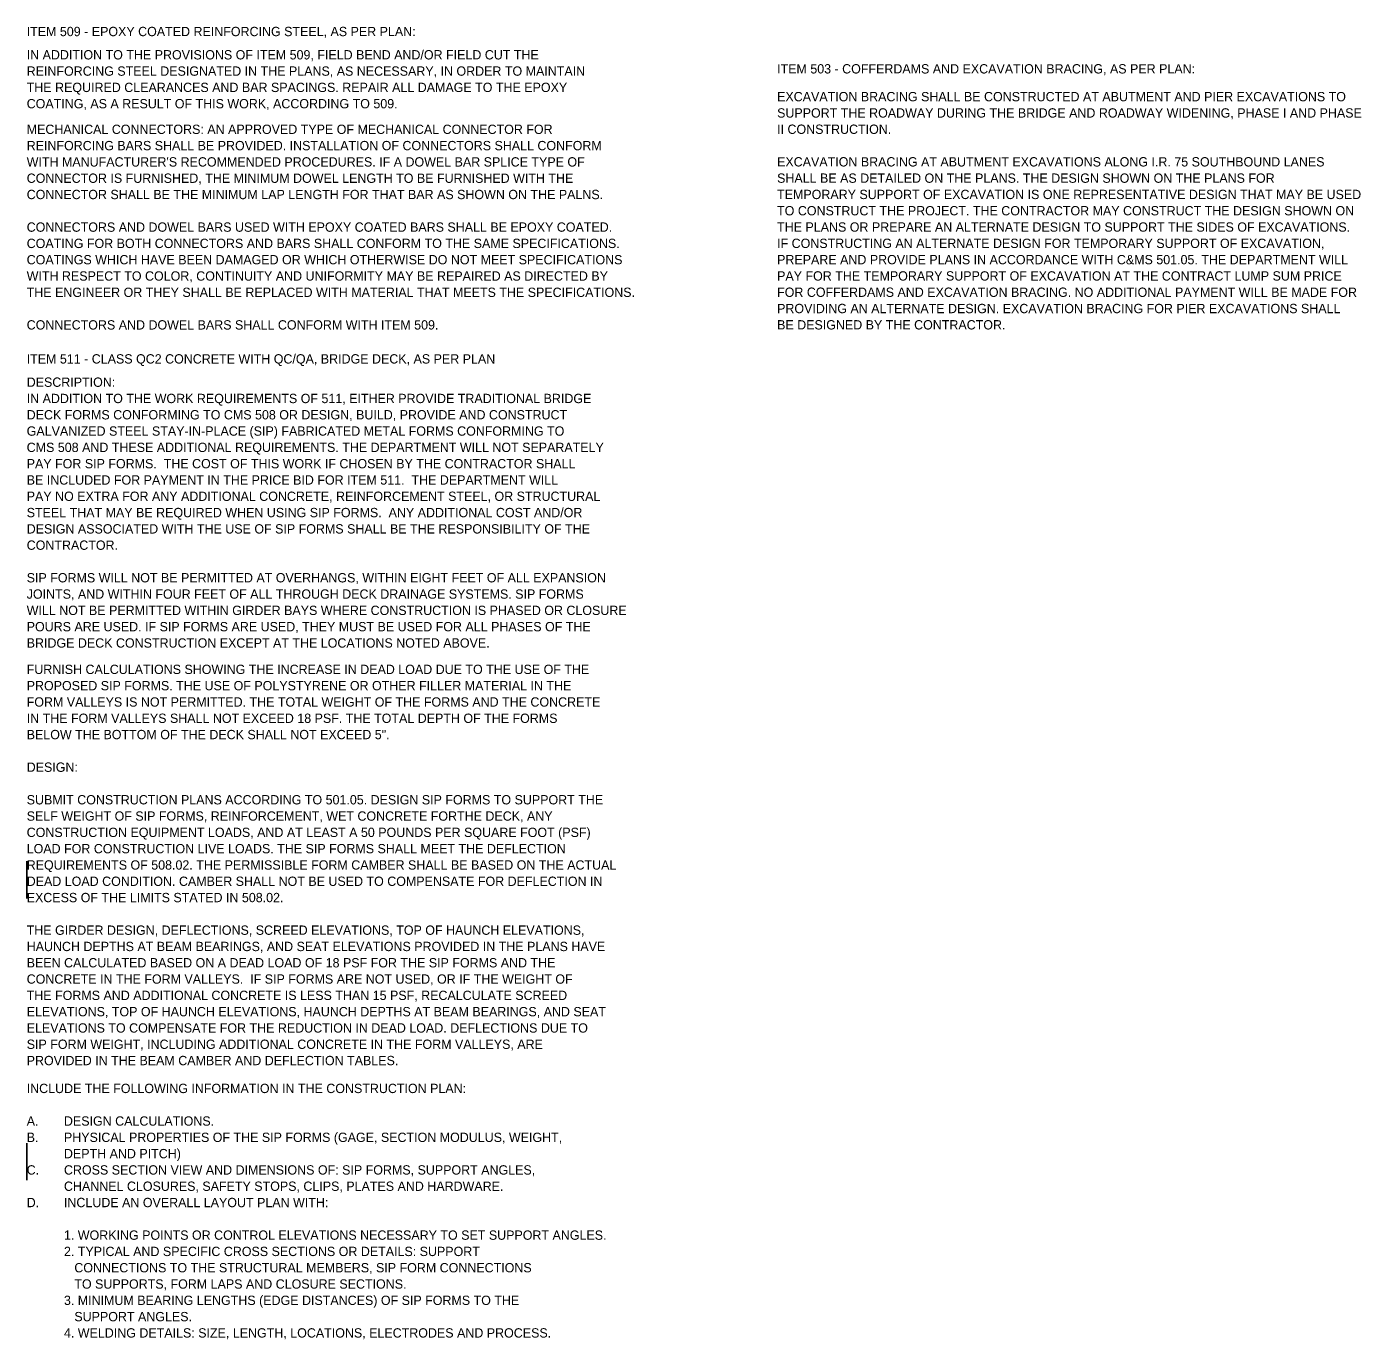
# Model space of a CAD drawing. Extents: x 1530552 to 1530730, y 675304 to 675366.
# Drawn here: x 1530590.11 to 1530610.17, y 675326.13 to 675345.86 of the extents above; entities that cross this region are included whole.
import ezdxf

# ---------------------------------------------------------------- set-up
doc = ezdxf.new("R2010")
doc.units = 0
doc.layers.add('BR_P_Gen_Text', color=7, linetype='Continuous')
doc.layers.add('SC_Scratch1', color=7, linetype='Continuous')

msp = doc.modelspace()

# ---------------------------------------------------------------- linework, layer by layer
at = {"layer": 'SC_Scratch1'}
for p, q in [((1530590.111, 675333.313), (1530590.111, 675332.753)), ((1530590.111, 675329.078), (1530590.111, 675328.518))]:
    msp.add_line(p, q, dxfattribs=at)

# ---------------------------------------------------------------- texts
at = {"layer": 'BR_P_Gen_Text'}
for s, p in [('ITEM 509 - EPOXY COATED REINFORCING STEEL, AS PER PLAN:', (1530590.111, 675345.716)), ('IN ADDITION TO THE PROVISIONS OF ITEM 509, FIELD BEND AND/OR FIELD CUT THE', (1530590.111, 675345.366)), ('ITEM 503 - COFFERDAMS AND EXCAVATION BRACING, AS PER PLAN:', (1530601.391, 675345.155)), ('REINFORCING STEEL DESIGNATED IN THE PLANS, AS NECESSARY, IN ORDER TO MAINTAIN', (1530590.111, 675345.121)), ('THE REQUIRED CLEARANCES AND BAR SPACINGS. REPAIR ALL DAMAGE TO THE EPOXY', (1530590.111, 675344.876)), ('COATING, AS A RESULT OF THIS WORK, ACCORDING TO 509.', (1530590.111, 675344.631)), ('EXCAVATION BRACING SHALL BE CONSTRUCTED AT ABUTMENT AND PIER EXCAVATIONS TO ', (1530601.391, 675344.737)), ('SUPPORT THE ROADWAY DURING THE BRIDGE AND ROADWAY WIDENING, PHASE I AND PHASE ', (1530601.391, 675344.492)), ('MECHANICAL CONNECTORS: AN APPROVED TYPE OF MECHANICAL CONNECTOR FOR', (1530590.111, 675344.246)), ('II CONSTRUCTION. ', (1530601.391, 675344.247)), ('REINFORCING BARS SHALL BE PROVIDED. INSTALLATION OF CONNECTORS SHALL CONFORM', (1530590.111, 675344.001)), ("WITH MANUFACTURER'S RECOMMENDED PROCEDURES. IF A DOWEL BAR SPLICE TYPE OF", (1530590.111, 675343.756)), ('EXCAVATION BRACING AT ABUTMENT EXCAVATIONS ALONG I.R. 75 SOUTHBOUND LANES ', (1530601.391, 675343.757)), ('CONNECTOR IS FURNISHED, THE MINIMUM DOWEL LENGTH TO BE FURNISHED WITH THE', (1530590.111, 675343.511)), ('SHALL BE AS DETAILED ON THE PLANS. THE DESIGN SHOWN ON THE PLANS FOR ', (1530601.391, 675343.512)), ('CONNECTOR SHALL BE THE MINIMUM LAP LENGTH FOR THAT BAR AS SHOWN ON THE PALNS.', (1530590.111, 675343.266)), ('TEMPORARY SUPPORT OF EXCAVATION IS ONE REPRESENTATIVE DESIGN THAT MAY BE USED ', (1530601.391, 675343.267)), ('TO CONSTRUCT THE PROJECT. THE CONTRACTOR MAY CONSTRUCT THE DESIGN SHOWN ON ', (1530601.391, 675343.022)), ('CONNECTORS AND DOWEL BARS USED WITH EPOXY COATED BARS SHALL BE EPOXY COATED.', (1530590.111, 675342.776)), ('THE PLANS OR PREPARE AN ALTERNATE DESIGN TO SUPPORT THE SIDES OF EXCAVATIONS. ', (1530601.391, 675342.777)), ('COATING FOR BOTH CONNECTORS AND BARS SHALL CONFORM TO THE SAME SPECIFICATIONS.', (1530590.111, 675342.531)), ('IF CONSTRUCTING AN ALTERNATE DESIGN FOR TEMPORARY SUPPORT OF EXCAVATION, ', (1530601.391, 675342.532)), ('COATINGS WHICH HAVE BEEN DAMAGED OR WHICH OTHERWISE DO NOT MEET SPECIFICATIONS', (1530590.111, 675342.286)), ('PREPARE AND PROVIDE PLANS IN ACCORDANCE WITH C&MS 501.05. THE DEPARTMENT WILL ', (1530601.391, 675342.287)), ('WITH RESPECT TO COLOR, CONTINUITY AND UNIFORMITY MAY BE REPAIRED AS DIRECTED BY', (1530590.111, 675342.041)), ('PAY FOR THE TEMPORARY SUPPORT OF EXCAVATION AT THE CONTRACT LUMP SUM PRICE ', (1530601.391, 675342.042)), ('THE ENGINEER OR THEY SHALL BE REPLACED WITH MATERIAL THAT MEETS THE SPECIFICATIONS.', (1530590.111, 675341.796)), ('FOR COFFERDAMS AND EXCAVATION BRACING. NO ADDITIONAL PAYMENT WILL BE MADE FOR ', (1530601.391, 675341.797)), ('PROVIDING AN ALTERNATE DESIGN. EXCAVATION BRACING FOR PIER EXCAVATIONS SHALL ', (1530601.391, 675341.552)), ('CONNECTORS AND DOWEL BARS SHALL CONFORM WITH ITEM 509.', (1530590.111, 675341.306)), ('BE DESIGNED BY THE CONTRACTOR.', (1530601.391, 675341.307)), ('ITEM 511 - CLASS QC2 CONCRETE WITH QC/QA, BRIDGE DECK, AS PER PLAN', (1530590.111, 675340.795)), ('DESCRIPTION:', (1530590.111, 675340.445)), ('IN ADDITION TO THE WORK REQUIREMENTS OF 511, EITHER PROVIDE TRADITIONAL BRIDGE ', (1530590.111, 675340.2)), ('DECK FORMS CONFORMING TO CMS 508 OR DESIGN, BUILD, PROVIDE AND CONSTRUCT ', (1530590.111, 675339.955)), ('GALVANIZED STEEL STAY-IN-PLACE (SIP) FABRICATED METAL FORMS CONFORMING TO ', (1530590.111, 675339.71)), ('CMS 508 AND THESE ADDITIONAL REQUIREMENTS. THE DEPARTMENT WILL NOT SEPARATELY ', (1530590.111, 675339.465)), ('PAY FOR SIP FORMS.  THE COST OF THIS WORK IF CHOSEN BY THE CONTRACTOR SHALL ', (1530590.111, 675339.22)), ('BE INCLUDED FOR PAYMENT IN THE PRICE BID FOR ITEM 511.  THE DEPARTMENT WILL ', (1530590.111, 675338.975)), ('PAY NO EXTRA FOR ANY ADDITIONAL CONCRETE, REINFORCEMENT STEEL, OR STRUCTURAL', (1530590.111, 675338.73)), ('STEEL THAT MAY BE REQUIRED WHEN USING SIP FORMS.  ANY ADDITIONAL COST AND/OR ', (1530590.111, 675338.485)), ('DESIGN ASSOCIATED WITH THE USE OF SIP FORMS SHALL BE THE RESPONSIBILITY OF THE', (1530590.111, 675338.24)), ('CONTRACTOR.  ', (1530590.111, 675337.995)), ('SIP FORMS WILL NOT BE PERMITTED AT OVERHANGS, WITHIN EIGHT FEET OF ALL EXPANSION', (1530590.111, 675337.505)), ('JOINTS, AND WITHIN FOUR FEET OF ALL THROUGH DECK DRAINAGE SYSTEMS. SIP FORMS ', (1530590.111, 675337.26)), ('WILL NOT BE PERMITTED WITHIN GIRDER BAYS WHERE CONSTRUCTION IS PHASED OR CLOSURE', (1530590.111, 675337.015)), ('POURS ARE USED. IF SIP FORMS ARE USED, THEY MUST BE USED FOR ALL PHASES OF THE ', (1530590.111, 675336.77)), ('BRIDGE DECK CONSTRUCTION EXCEPT AT THE LOCATIONS NOTED ABOVE.', (1530590.111, 675336.525)), ('FURNISH CALCULATIONS SHOWING THE INCREASE IN DEAD LOAD DUE TO THE USE OF THE ', (1530590.111, 675336.128)), ('PROPOSED SIP FORMS. THE USE OF POLYSTYRENE OR OTHER FILLER MATERIAL IN THE ', (1530590.111, 675335.883)), ('FORM VALLEYS IS NOT PERMITTED. THE TOTAL WEIGHT OF THE FORMS AND THE CONCRETE ', (1530590.111, 675335.638)), ('IN THE FORM VALLEYS SHALL NOT EXCEED 18 PSF. THE TOTAL DEPTH OF THE FORMS ', (1530590.111, 675335.393)), ('BELOW THE BOTTOM OF THE DECK SHALL NOT EXCEED 5".', (1530590.111, 675335.148)), ('DESIGN:', (1530590.111, 675334.658)), ('SUBMIT CONSTRUCTION PLANS ACCORDING TO 501.05. DESIGN SIP FORMS TO SUPPORT THE', (1530590.111, 675334.168)), ('SELF WEIGHT OF SIP FORMS, REINFORCEMENT, WET CONCRETE FORTHE DECK, ANY ', (1530590.111, 675333.923)), ('CONSTRUCTION EQUIPMENT LOADS, AND AT LEAST A 50 POUNDS PER SQUARE FOOT (PSF)', (1530590.111, 675333.678)), ('LOAD FOR CONSTRUCTION LIVE LOADS. THE SIP FORMS SHALL MEET THE DEFLECTION ', (1530590.111, 675333.433)), ('REQUIREMENTS OF 508.02. THE PERMISSIBLE FORM CAMBER SHALL BE BASED ON THE ACTUAL', (1530590.111, 675333.188)), ('DEAD LOAD CONDITION. CAMBER SHALL NOT BE USED TO COMPENSATE FOR DEFLECTION IN ', (1530590.111, 675332.943)), ('EXCESS OF THE LIMITS STATED IN 508.02.', (1530590.111, 675332.698)), ('THE GIRDER DESIGN, DEFLECTIONS, SCREED ELEVATIONS, TOP OF HAUNCH ELEVATIONS, ', (1530590.111, 675332.208)), ('HAUNCH DEPTHS AT BEAM BEARINGS, AND SEAT ELEVATIONS PROVIDED IN THE PLANS HAVE ', (1530590.111, 675331.963)), ('BEEN CALCULATED BASED ON A DEAD LOAD OF 18 PSF FOR THE SIP FORMS AND THE ', (1530590.111, 675331.718)), ('CONCRETE IN THE FORM VALLEYS.  IF SIP FORMS ARE NOT USED, OR IF THE WEIGHT OF ', (1530590.111, 675331.473)), ('THE FORMS AND ADDITIONAL CONCRETE IS LESS THAN 15 PSF, RECALCULATE SCREED ', (1530590.111, 675331.228)), ('ELEVATIONS, TOP OF HAUNCH ELEVATIONS, HAUNCH DEPTHS AT BEAM BEARINGS, AND SEAT ', (1530590.111, 675330.983)), ('ELEVATIONS TO COMPENSATE FOR THE REDUCTION IN DEAD LOAD. DEFLECTIONS DUE TO ', (1530590.111, 675330.738)), ('SIP FORM WEIGHT, INCLUDING ADDITIONAL CONCRETE IN THE FORM VALLEYS, ARE ', (1530590.111, 675330.493)), ('PROVIDED IN THE BEAM CAMBER AND DEFLECTION TABLES.', (1530590.111, 675330.248)), ('INCLUDE THE FOLLOWING INFORMATION IN THE CONSTRUCTION PLAN:', (1530590.111, 675329.829)), ('INCLUDE THE FOLLOWING INFORMATION IN THE CONSTRUCTION PLAN:', (1530590.111, 675329.829)), ('A.', (1530590.111, 675329.339)), ('A.', (1530590.111, 675329.339)), ('DESIGN CALCULATIONS.', (1530590.671, 675329.339)), ('DESIGN CALCULATIONS.', (1530590.671, 675329.339)), ('B.', (1530590.111, 675329.094)), ('B.', (1530590.111, 675329.094)), ('PHYSICAL PROPERTIES OF THE SIP FORMS (GAGE, SECTION MODULUS, WEIGHT,', (1530590.671, 675329.094)), ('PHYSICAL PROPERTIES OF THE SIP FORMS (GAGE, SECTION MODULUS, WEIGHT,', (1530590.671, 675329.094)), ('DEPTH AND PITCH)', (1530590.671, 675328.849)), ('DEPTH AND PITCH)', (1530590.671, 675328.849)), ('C.', (1530590.111, 675328.604)), ('C.', (1530590.111, 675328.604)), ('CROSS SECTION VIEW AND DIMENSIONS OF: SIP FORMS, SUPPORT ANGLES,', (1530590.671, 675328.604)), ('CROSS SECTION VIEW AND DIMENSIONS OF: SIP FORMS, SUPPORT ANGLES,', (1530590.671, 675328.604)), ('CHANNEL CLOSURES, SAFETY STOPS, CLIPS, PLATES AND HARDWARE.', (1530590.671, 675328.359)), ('CHANNEL CLOSURES, SAFETY STOPS, CLIPS, PLATES AND HARDWARE.', (1530590.671, 675328.359)), ('D.', (1530590.111, 675328.114)), ('D.', (1530590.111, 675328.114)), ('INCLUDE AN OVERALL LAYOUT PLAN WITH:', (1530590.671, 675328.114)), ('INCLUDE AN OVERALL LAYOUT PLAN WITH:', (1530590.671, 675328.114)), ('1. WORKING POINTS OR CONTROL ELEVATIONS NECESSARY TO SET SUPPORT ANGLES. ', (1530590.671, 675327.624)), ('1. WORKING POINTS OR CONTROL ELEVATIONS NECESSARY TO SET SUPPORT ANGLES. ', (1530590.671, 675327.624)), ('2. TYPICAL AND SPECIFIC CROSS SECTIONS OR DETAILS: SUPPORT', (1530590.671, 675327.379)), ('2. TYPICAL AND SPECIFIC CROSS SECTIONS OR DETAILS: SUPPORT', (1530590.671, 675327.379)), ('   CONNECTIONS TO THE STRUCTURAL MEMBERS, SIP FORM CONNECTIONS', (1530590.671, 675327.134)), ('   CONNECTIONS TO THE STRUCTURAL MEMBERS, SIP FORM CONNECTIONS', (1530590.671, 675327.134)), ('   TO SUPPORTS, FORM LAPS AND CLOSURE SECTIONS.', (1530590.671, 675326.889)), ('   TO SUPPORTS, FORM LAPS AND CLOSURE SECTIONS.', (1530590.671, 675326.889)), ('3. MINIMUM BEARING LENGTHS (EDGE DISTANCES) OF SIP FORMS TO THE', (1530590.671, 675326.644)), ('3. MINIMUM BEARING LENGTHS (EDGE DISTANCES) OF SIP FORMS TO THE', (1530590.671, 675326.644)), ('   SUPPORT ANGLES.', (1530590.671, 675326.399)), ('   SUPPORT ANGLES.', (1530590.671, 675326.399)), ('4. WELDING DETAILS: SIZE, LENGTH, LOCATIONS, ELECTRODES AND PROCESS.', (1530590.671, 675326.154)), ('4. WELDING DETAILS: SIZE, LENGTH, LOCATIONS, ELECTRODES AND PROCESS.', (1530590.671, 675326.154))]:
    msp.add_text(s, height=0.14, dxfattribs=at).set_placement(p)

doc.saveas('drawing.dxf')
